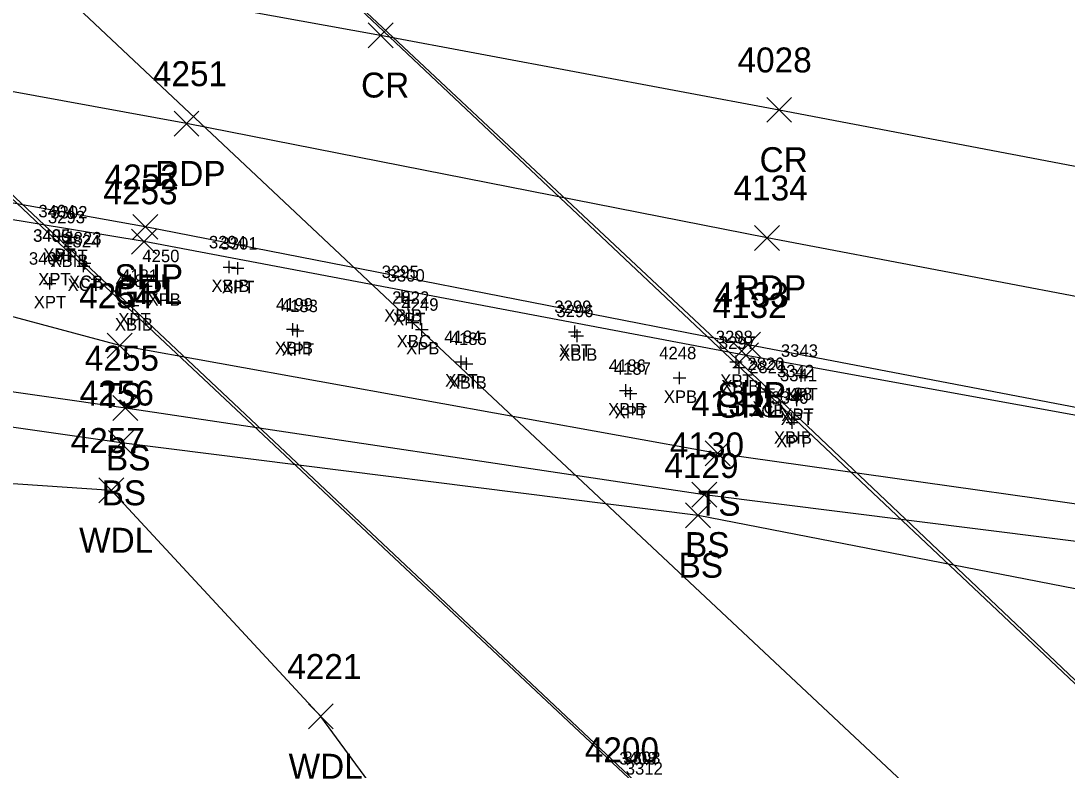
# Model space of a CAD drawing. Extents: x 1647574 to 1652703, y 212895 to 228670.
# Drawn here: x 1648950.8 to 1649034.7, y 227078.5 to 227138.6 of the extents above; entities that cross this region are included whole.
import ezdxf

# ---------------------------------------------------------------- set-up
doc = ezdxf.new("R2010")
doc.units = 0
for name, color, linetype in [('B_A', 7, 'Continuous'), ('B_I', 7, 'Continuous'), ('B_TIC', 7, 'Continuous'), ('BDC', 7, 'Continuous'), ('BELB', 7, 'Continuous'), ('L_A', 7, 'Continuous'), ('L_I', 7, 'Continuous'), ('L_TIC', 7, 'Continuous'), ('LAWA', 7, 'Continuous'), ('LELB', 7, 'Continuous'), ('P_A', 7, 'Continuous'), ('P_I', 7, 'Continuous'), ('P_TIC', 7, 'Continuous'), ('PET', 7, 'Continuous'), ('PRC', 7, 'Continuous'), ('PSP', 7, 'Continuous'), ('R_A', 7, 'Continuous'), ('R_I', 7, 'Continuous'), ('R_TIC', 7, 'Continuous'), ('RGR', 7, 'Continuous')]:
    doc.layers.add(name, color=color, linetype=linetype)

msp = doc.modelspace()

# ---------------------------------------------------------------- linework, layer by layer
at = {"layer": 'B_TIC'}
for p, q in [((1648953.908, 227121.37), (1648953.984, 227121.37)), ((1648954.633, 227120.888), (1648954.709, 227120.888)), ((1648954.869, 227121.28), (1648954.944, 227121.28)), ((1648953.499, 227119.415), (1648953.575, 227119.415)), ((1648953.503, 227119.405), (1648953.579, 227119.405)), ((1648955.955, 227119.198), (1648956.031, 227119.198)), ((1648955.86, 227118.961), (1648955.935, 227118.961)), ((1648967.547, 227118.882), (1648967.622, 227118.882)), ((1648968.228, 227118.779), (1648968.303, 227118.779)), ((1648953.148, 227117.571), (1648953.224, 227117.571)), ((1648962.252, 227117.774), (1648962.328, 227117.774)), ((1648959.807, 227115.785), (1648959.883, 227115.785)), ((1648959.927, 227116.191), (1648960.003, 227116.191)), ((1648981.399, 227116.501), (1648981.475, 227116.501)), ((1648981.962, 227116.212), (1648982.038, 227116.212)), ((1648982.235, 227114.435), (1648982.31, 227114.435)), ((1648972.642, 227113.891), (1648972.718, 227113.891)), ((1648973.026, 227113.764), (1648973.101, 227113.764)), ((1648982.987, 227113.875), (1648983.062, 227113.875)), ((1648995.25, 227113.694), (1648995.326, 227113.694)), ((1648995.441, 227113.362), (1648995.516, 227113.362)), ((1648986.137, 227111.289), (1648986.212, 227111.289)), ((1648986.573, 227111.129), (1648986.649, 227111.129)), ((1649008.189, 227111.277), (1649008.264, 227111.277)), ((1649008.432, 227110.81), (1649008.507, 227110.81)), ((1649003.654, 227109.984), (1649003.73, 227109.984)), ((1649013.411, 227110.182), (1649013.486, 227110.182)), ((1649010.767, 227109.119), (1649010.843, 227109.119)), ((1648999.351, 227108.977), (1648999.426, 227108.977)), ((1648999.733, 227108.742), (1648999.808, 227108.742)), ((1649010.58, 227108.866), (1649010.656, 227108.866)), ((1649013.051, 227108.22), (1649013.127, 227108.22)), ((1649013.101, 227108.535), (1649013.176, 227108.535)), ((1649012.651, 227106.704), (1649012.727, 227106.704)), ((1649012.692, 227106.414), (1649012.768, 227106.414))]:
    msp.add_line(p, q, dxfattribs=at)
for points in [[(1648953.905, 227120.87), (1648953.905, 227121.87)], [(1648954.865, 227120.78), (1648954.865, 227121.78)], [(1648953.405, 227121.37), (1648954.405, 227121.37)], [(1648954.13, 227120.888), (1648955.13, 227120.888)], [(1648954.365, 227121.28), (1648955.365, 227121.28)], [(1648954.63, 227120.388), (1648954.63, 227121.388)], [(1648953.496, 227118.915), (1648953.496, 227119.915)], [(1648953.5, 227118.905), (1648953.5, 227119.905)], [(1648952.996, 227119.415), (1648953.996, 227119.415)], [(1648953, 227119.405), (1648954, 227119.405)], [(1648955.452, 227119.198), (1648956.452, 227119.198)], [(1648955.856, 227118.461), (1648955.856, 227119.461)], [(1648955.952, 227118.698), (1648955.952, 227119.698)], [(1648967.543, 227118.382), (1648967.543, 227119.382)], [(1648968.224, 227118.279), (1648968.224, 227119.279)], [(1648955.356, 227118.961), (1648956.356, 227118.961)], [(1648962.249, 227117.274), (1648962.249, 227118.274)], [(1648967.043, 227118.882), (1648968.043, 227118.882)], [(1648967.724, 227118.779), (1648968.724, 227118.779)], [(1648952.645, 227117.571), (1648953.645, 227117.571)], [(1648953.145, 227117.071), (1648953.145, 227118.071)], [(1648961.749, 227117.774), (1648962.749, 227117.774)], [(1648959.924, 227115.691), (1648959.924, 227116.691)], [(1648981.396, 227116.001), (1648981.396, 227117.001)], [(1648981.959, 227115.712), (1648981.959, 227116.712)], [(1648959.304, 227115.785), (1648960.304, 227115.785)], [(1648959.424, 227116.191), (1648960.424, 227116.191)], [(1648959.804, 227115.285), (1648959.804, 227116.285)], [(1648980.896, 227116.501), (1648981.896, 227116.501)], [(1648981.459, 227116.212), (1648982.459, 227116.212)], [(1648982.231, 227113.935), (1648982.231, 227114.935)], [(1648972.639, 227113.391), (1648972.639, 227114.391)], [(1648973.022, 227113.264), (1648973.022, 227114.264)], [(1648981.731, 227114.435), (1648982.731, 227114.435)], [(1648982.983, 227113.375), (1648982.983, 227114.375)], [(1648995.247, 227113.194), (1648995.247, 227114.194)], [(1648972.139, 227113.891), (1648973.139, 227113.891)], [(1648972.522, 227113.764), (1648973.522, 227113.764)], [(1648982.483, 227113.875), (1648983.483, 227113.875)], [(1648994.747, 227113.694), (1648995.747, 227113.694)], [(1648994.937, 227113.362), (1648995.937, 227113.362)], [(1648995.437, 227112.862), (1648995.437, 227113.862)], [(1648986.133, 227110.789), (1648986.133, 227111.789)], [(1648986.57, 227110.629), (1648986.57, 227111.629)], [(1649008.185, 227110.777), (1649008.185, 227111.777)], [(1648985.633, 227111.289), (1648986.633, 227111.289)], [(1648986.07, 227111.129), (1648987.07, 227111.129)], [(1649007.685, 227111.277), (1649008.685, 227111.277)], [(1649007.928, 227110.81), (1649008.928, 227110.81)], [(1649008.428, 227110.31), (1649008.428, 227111.31)], [(1649013.407, 227109.682), (1649013.407, 227110.682)], [(1649003.151, 227109.984), (1649004.151, 227109.984)], [(1649003.651, 227109.484), (1649003.651, 227110.484)], [(1649012.907, 227110.182), (1649013.907, 227110.182)], [(1648999.347, 227108.477), (1648999.347, 227109.477)], [(1648999.729, 227108.242), (1648999.729, 227109.242)], [(1649010.264, 227109.119), (1649011.264, 227109.119)], [(1649010.577, 227108.366), (1649010.577, 227109.366)], [(1649010.764, 227108.619), (1649010.764, 227109.619)], [(1649013.097, 227108.035), (1649013.097, 227109.035)], [(1648998.847, 227108.977), (1648999.847, 227108.977)], [(1648999.229, 227108.742), (1649000.229, 227108.742)], [(1649010.077, 227108.866), (1649011.077, 227108.866)], [(1649012.548, 227108.22), (1649013.548, 227108.22)], [(1649012.597, 227108.535), (1649013.597, 227108.535)], [(1649013.048, 227107.72), (1649013.048, 227108.72)], [(1649012.148, 227106.704), (1649013.148, 227106.704)], [(1649012.648, 227106.204), (1649012.648, 227107.204)], [(1649012.689, 227105.914), (1649012.689, 227106.914)], [(1649012.189, 227106.414), (1649013.189, 227106.414)]]:
    msp.add_lwpolyline(points, dxfattribs=at)
at = {"layer": 'BDC'}
for points in [[(1648651.076, 227406.804), (1648690.742, 227369.256), (1648733.458, 227328.853), (1648776.322, 227288.427), (1648833.713, 227234.413), (1648891.304, 227180.165), (1648955.952, 227119.198), (1649002.814, 227075.033), (1649045.282, 227034.879)], [(1648650.624, 227406.773), (1648690.525, 227369.254), (1648733.472, 227328.732), (1648776.312, 227288.32), (1648833.664, 227234.301), (1648891.231, 227180.054), (1648955.856, 227118.961), (1649002.635, 227075.018), (1649045.277, 227034.596)], [(1648705.852, 227396.154), (1648745.059, 227359.411), (1648787.916, 227318.711), (1648830.863, 227278.3), (1648888.33, 227224.067), (1648945.958, 227169.85), (1649010.577, 227108.866), (1649057.241, 227064.803), (1649099.962, 227024.603)], [(1648705.902, 227396.256), (1648745.142, 227359.215), (1648788.072, 227318.717), (1648831.078, 227278.232), (1648888.572, 227223.976), (1648945.897, 227169.932), (1649010.764, 227109.119), (1649057.374, 227064.845), (1649100.019, 227024.673)]]:
    msp.add_lwpolyline(points, dxfattribs=at)
at = {"layer": 'BELB'}
msp.add_lwpolyline([(1648676.128, 227401.909), (1648716.738, 227364.514), (1648759.552, 227324.27), (1648803.456, 227283.214), (1648860.317, 227229.513), (1648917.836, 227175.012), (1648982.231, 227114.435), (1649029.643, 227069.952), (1649071.001, 227030.272)], dxfattribs=at)
at = {"layer": 'L_TIC'}
for points in [[(1648957.761, 227111.582), (1648959.761, 227113.582)], [(1648959.761, 227111.582), (1648957.761, 227113.582)], [(1648958.216, 227106.566), (1648960.216, 227108.566)], [(1648960.216, 227106.566), (1648958.216, 227108.566)], [(1648957.862, 227103.769), (1648959.862, 227105.769)], [(1648959.862, 227103.769), (1648957.862, 227105.769)], [(1649005.716, 227102.933), (1649007.716, 227104.933)], [(1649007.716, 227102.933), (1649005.716, 227104.933)], [(1648957.087, 227099.964), (1648959.087, 227101.964)], [(1648959.087, 227099.964), (1648957.087, 227101.964)], [(1649004.649, 227099.613), (1649006.649, 227101.613)], [(1649006.649, 227099.613), (1649004.649, 227101.613)], [(1649004.132, 227097.96), (1649006.132, 227099.96)], [(1649006.132, 227097.96), (1649004.132, 227099.96)], [(1648973.887, 227081.833), (1648975.887, 227083.833)], [(1648975.887, 227081.833), (1648973.887, 227083.833)]]:
    msp.add_lwpolyline(points, dxfattribs=at)
at = {"layer": 'LAWA'}
msp.add_lwpolyline([(1649030.642, 227023.855), (1649020.978, 227035.136), (1648998.908, 227050.079), (1648974.887, 227082.833), (1648958.087, 227100.964), (1648931.997, 227102.731), (1648925.379, 227109.578), (1648919.509, 227113.251), (1648913.128, 227119.189), (1648871.872, 227126.889), (1648832.667, 227127.944), (1648783.368, 227137.077)], dxfattribs=at)
at = {"layer": 'LELB'}
for points in [[(1649303.944, 227051.179), (1649261.071, 227060.393), (1649216.61, 227069.452), (1649178.247, 227076.125), (1649140.517, 227081.324), (1649094.47, 227090.055), (1649051.01, 227097.653), (1649006.716, 227103.933), (1648958.761, 227112.582), (1648914.479, 227124.455), (1648876.092, 227132.196), (1648833.458, 227141.48), (1648786.832, 227153.426)], [(1649303.061, 227047.281), (1649260.976, 227055.31), (1649217.959, 227064.405), (1649177.848, 227072.418), (1649139.313, 227077.282), (1649094.119, 227086.638), (1649050.125, 227095.02), (1649005.649, 227100.613), (1648959.216, 227107.566), (1648919.509, 227113.251), (1648868.975, 227116.788), (1648831.484, 227119.829), (1648781.157, 227125.897)], [(1649302.967, 227044.784), (1649260.667, 227052.978), (1649215.103, 227059.721), (1649174.919, 227066.322), (1649138.434, 227073.451), (1649092.927, 227081.317), (1649048.986, 227090.42), (1649005.132, 227098.96), (1648958.862, 227104.769), (1648925.379, 227109.578), (1648868.507, 227114.828), (1648832.143, 227115.066)]]:
    msp.add_lwpolyline(points, dxfattribs=at)
at = {"layer": 'P_TIC'}
for points in [[(1648978.678, 227136.482), (1648980.678, 227138.482)], [(1648980.678, 227136.482), (1648978.678, 227138.482)], [(1649010.638, 227130.497), (1649012.638, 227132.497)], [(1649012.638, 227130.497), (1649010.638, 227132.497)], [(1648963.113, 227129.393), (1648965.113, 227131.393)], [(1648965.113, 227129.393), (1648963.113, 227131.393)], [(1648959.805, 227121.107), (1648961.805, 227123.107)], [(1648961.805, 227121.107), (1648959.805, 227123.107)], [(1649009.671, 227120.221), (1649011.671, 227122.221)], [(1649011.671, 227120.221), (1649009.671, 227122.221)], [(1649008.15, 227111.651), (1649010.15, 227113.651)], [(1649010.15, 227111.651), (1649008.15, 227113.651)]]:
    msp.add_lwpolyline(points, dxfattribs=at)
at = {"layer": 'PET'}
msp.add_lwpolyline([(1649306.683, 227064.126), (1649262.992, 227072.364), (1649217.787, 227081.095), (1649180.877, 227089.297), (1649143.905, 227096.661), (1649097.056, 227105.071), (1649054.531, 227112.891), (1649010.671, 227121.221), (1648964.113, 227130.393), (1648922.422, 227138.031), (1648885.035, 227145.377), (1648836.169, 227155.583), (1648791.114, 227166.692)], dxfattribs=at)
at = {"layer": 'PRC'}
msp.add_lwpolyline([(1648578.474, 227245.088), (1648614.144, 227232.377), (1648658.376, 227217.212), (1648693.17, 227205.447), (1648728.772, 227194.614), (1648764.162, 227184.595), (1648791.485, 227177.326), (1648822.259, 227169.584), (1648868.208, 227159.379), (1648902.01, 227152.53), (1648938.677, 227144.922), (1648979.678, 227137.482), (1649011.638, 227131.497), (1649049.006, 227124.369), (1649090.363, 227116.947), (1649126.936, 227110.347), (1649164.154, 227103.487), (1649199.467, 227096.77), (1649251.628, 227086.358), (1649284.276, 227080.21), (1649307.757, 227075.596)], dxfattribs=at)
at = {"layer": 'PSP'}
msp.add_lwpolyline([(1649305.229, 227055.054), (1649261.488, 227063.436), (1649216.568, 227072.89), (1649179.118, 227080.226), (1649141.321, 227088.231), (1649095.571, 227096.469), (1649052.889, 227104.283), (1649009.15, 227112.651), (1648960.805, 227122.107), (1648921.899, 227129.088), (1648883.471, 227136.6), (1648833.933, 227146.375), (1648787.9, 227157.815)], dxfattribs=at)
at = {"layer": 'R_TIC'}
for points in [[(1648959.707, 227119.918), (1648961.707, 227121.918)], [(1648961.707, 227119.918), (1648959.707, 227121.918)], [(1649007.982, 227110.793), (1649009.982, 227112.793)], [(1649009.982, 227110.793), (1649007.982, 227112.793)]]:
    msp.add_lwpolyline(points, dxfattribs=at)
at = {"layer": 'RGR'}
msp.add_lwpolyline([(1649151.879, 227085.073), (1649138.949, 227087.713), (1649095.344, 227095.692), (1649052.831, 227103.816), (1649008.982, 227111.793), (1648960.707, 227120.918), (1648940.449, 227124.284)], dxfattribs=at)

# ---------------------------------------------------------------- texts
at = {"layer": 'B_A'}
for s, p in [('XPT', (1648952.625, 227119.37)), ('XPT', (1648953.586, 227119.28)), ('XBIB', (1648953.2, 227118.888)), ('XPT', (1648952.216, 227117.415)), ('XPT', (1648952.22, 227117.405)), ('XCT', (1648954.577, 227116.961)), ('XCB', (1648954.688, 227117.198)), ('XBIB', (1648966.114, 227116.882)), ('XPT', (1648966.945, 227116.779)), ('XPT', (1648951.865, 227115.571)), ('XPB', (1648960.985, 227115.774)), ('XPT', (1648958.644, 227114.191)), ('XBIB', (1648979.967, 227114.501)), ('XPT', (1648980.679, 227114.212)), ('XBIB', (1648958.375, 227113.785)), ('XBC', (1648980.967, 227112.435)), ('XBIB', (1648971.21, 227111.891)), ('XPT', (1648971.743, 227111.764)), ('XPB', (1648981.719, 227111.875)), ('XPT', (1648993.967, 227111.694)), ('XBIB', (1648994.008, 227111.362)), ('XPT', (1648984.854, 227109.289)), ('XBIB', (1648985.141, 227109.129)), ('XPT', (1649006.906, 227109.277)), ('XBIB', (1649006.999, 227108.81)), ('XPT', (1649012.128, 227108.182)), ('XPB', (1649002.387, 227107.984)), ('XBIB', (1648997.918, 227106.977)), ('XPT', (1648998.45, 227106.742)), ('XCB', (1649009.313, 227106.866)), ('XCT', (1649009.484, 227107.119)), ('XPT', (1649011.818, 227106.535)), ('XPT', (1649011.768, 227106.22)), ('XBIB', (1649011.219, 227104.704)), ('XPT', (1649011.409, 227104.414))]:
    msp.add_text(s, height=1, dxfattribs=at).set_placement(p)
at = {"layer": 'B_I'}
for s, p in [('3404', (1648952.236, 227122.87)), ('3293', (1648953, 227122.388)), ('3302', (1648953.196, 227122.78)), ('3406', (1648951.803, 227120.905)), ('3405', (1648951.827, 227120.915)), ('2823', (1648954.322, 227120.698)), ('2824', (1648954.227, 227120.461)), ('3294', (1648965.914, 227120.382)), ('3301', (1648966.838, 227120.279)), ('3407', (1648951.475, 227119.071)), ('4250', (1648960.575, 227119.274)), ('4182', (1648958.457, 227117.285)), ('4181', (1648958.861, 227117.691)), ('3295', (1648979.766, 227118.001)), ('3300', (1648980.246, 227117.712)), ('2822', (1648980.601, 227115.935)), ('4199', (1648971.288, 227115.391)), ('4183', (1648971.676, 227115.264)), ('4249', (1648981.349, 227115.375)), ('3299', (1648993.613, 227115.194)), ('3296', (1648993.78, 227114.862)), ('4184', (1648984.787, 227112.789)), ('4185', (1648985.223, 227112.629)), ('3298', (1649006.556, 227112.777)), ('3297', (1649006.798, 227112.31)), ('4248', (1649002.021, 227111.484)), ('3343', (1649011.777, 227111.682)), ('2820', (1649009.09, 227110.619)), ('4186', (1648997.973, 227110.477)), ('4187', (1648998.383, 227110.242)), ('2821', (1649009.23, 227110.366)), ('3342', (1649011.467, 227110.035)), ('3341', (1649011.701, 227109.72)), ('4188', (1649011.302, 227108.204)), ('3340', (1649011.016, 227107.914)), ('3408', (1648998.811, 227078.971)), ('3303', (1648999.143, 227079.009)), ('3312', (1648999.339, 227078.162))]:
    msp.add_text(s, height=1, dxfattribs=at).set_placement(p)
at = {"layer": 'L_A'}
for s, p in [('TS', (1648957.171, 227107.582)), ('BS', (1648957.657, 227102.566)), ('BS', (1648957.303, 227099.769)), ('TS', (1649005.125, 227098.933)), ('WDL', (1648955.504, 227095.964)), ('BS', (1649004.09, 227095.613)), ('BS', (1649003.573, 227093.96)), ('WDL', (1648972.304, 227077.833))]:
    msp.add_text(s, height=2, dxfattribs=at).set_placement(p)
at = {"layer": 'L_I'}
for s, p in [('4254', (1648955.501, 227115.582)), ('4255', (1648955.956, 227110.566)), ('4256', (1648955.547, 227107.769)), ('4131', (1649004.59, 227106.933)), ('4257', (1648954.827, 227103.964)), ('4130', (1649002.87, 227103.613)), ('4129', (1649002.431, 227101.96)), ('4221', (1648972.194, 227085.833)), ('4200', (1648996.055, 227079.147))]:
    msp.add_text(s, height=2, dxfattribs=at).set_placement(p)
at = {"layer": 'P_A'}
for s, p in [('CR', (1648978.111, 227132.482)), ('CR', (1649010.071, 227126.497)), ('RDP', (1648961.601, 227125.393)), ('SHP', (1648958.34, 227117.107)), ('RDP', (1649008.16, 227116.221)), ('SHP', (1649006.686, 227107.651))]:
    msp.add_text(s, height=2, dxfattribs=at).set_placement(p)
at = {"layer": 'P_I'}
for s, p in [('4028', (1649008.299, 227134.497)), ('4251', (1648961.42, 227133.393)), ('4252', (1648957.545, 227125.107)), ('4134', (1649007.979, 227124.221)), ('4133', (1649006.458, 227115.651))]:
    msp.add_text(s, height=2, dxfattribs=at).set_placement(p)
at = {"layer": 'R_A'}
for p in [(1648958.25, 227115.918), (1649006.525, 227106.793)]:
    msp.add_text('GRL', height=2, dxfattribs=at).set_placement(p)
at = {"layer": 'R_I'}
for s, p in [('4253', (1648957.447, 227123.918)), ('4132', (1649006.289, 227114.793))]:
    msp.add_text(s, height=2, dxfattribs=at).set_placement(p)

doc.saveas('drawing.dxf')
